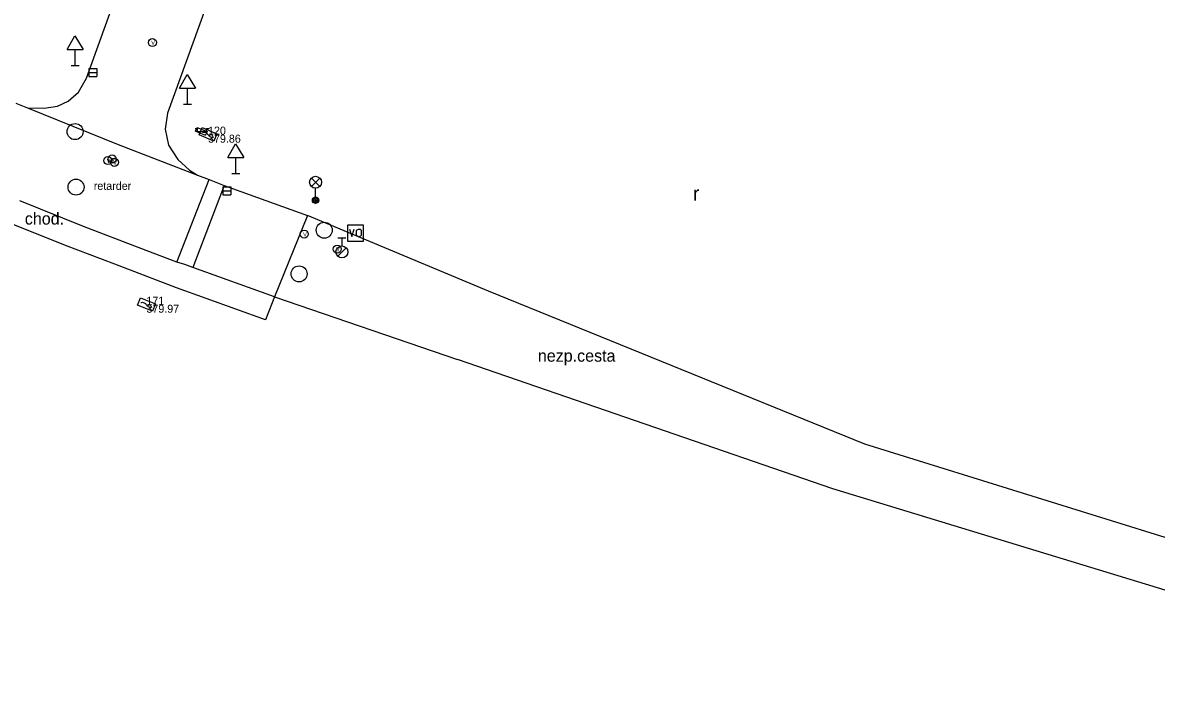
# Model space of a CAD drawing. Extents: x -836568 to -836015, y -1070547 to -1070212.
# Drawn here: x -836298.6 to -836227.7, y -1070464.9 to -1070423.4 of the extents above; entities that cross this region are included whole.
import ezdxf

# ---------------------------------------------------------------- set-up
doc = ezdxf.new("R2010")
doc.units = 0
for name, color, linetype in [('BodPole_mer', 7, 'Continuous'), ('BodPole_popis', 7, 'Continuous'), ('Doprava_body', 7, 'Continuous'), ('Doprava_hranice', 7, 'Continuous'), ('Doprava_kody', 7, 'Continuous'), ('Doprava_popis', 7, 'Continuous'), ('OstPloch_kody', 7, 'Continuous'), ('PovrZnIS_body', 7, 'Continuous'), ('PovrZnIS_hranice', 7, 'Continuous'), ('PovrZnIS_kody', 7, 'Continuous')]:
    doc.layers.add(name, color=color, linetype=linetype)

msp = doc.modelspace()

# ---------------------------------------------------------------- linework, layer by layer
at = {"layer": 'BodPole_mer'}
for p, q in [((-836290.47, -1070424.65), (-836290.47, -1070424.65)), ((-836295.29, -1070426.08), (-836295.29, -1070426.08)), ((-836294.58, -1070426.87), (-836294.58, -1070426.87)), ((-836294.18, -1070426.53), (-836294.18, -1070426.53)), ((-836295.74, -1070428.32), (-836295.74, -1070428.32)), ((-836295.08, -1070427.75), (-836295.08, -1070427.75)), ((-836298.27, -1070428.74), (-836298.27, -1070428.74)), ((-836297.24, -1070428.75), (-836297.24, -1070428.75)), ((-836296.4, -1070428.62), (-836296.4, -1070428.62)), ((-836288.27, -1070428.5), (-836288.27, -1070428.5)), ((-836289.53, -1070429.07), (-836289.53, -1070429.07)), ((-836295.3, -1070430.22), (-836295.3, -1070430.22)), ((-836289.67, -1070430.07), (-836289.67, -1070430.07)), ((-836287.77, -1070430.19), (-836287.77, -1070430.19)), ((-836287.77, -1070430.19), (-836287.77, -1070430.19)), ((-836287.67, -1070429.96), (-836287.67, -1070429.96)), ((-836287.67, -1070429.96), (-836287.67, -1070429.96)), ((-836287.15, -1070430.45), (-836287.15, -1070430.45)), ((-836287.15, -1070430.45), (-836287.15, -1070430.45)), ((-836287.05, -1070430.22), (-836287.05, -1070430.22)), ((-836287.05, -1070430.22), (-836287.05, -1070430.22)), ((-836286.99, -1070430.41), (-836286.99, -1070430.41)), ((-836292.61, -1070431.02), (-836292.61, -1070431.02)), ((-836289.47, -1070431.07), (-836289.47, -1070431.07)), ((-836293.25, -1070432.03), (-836293.25, -1070432.03)), ((-836292.98, -1070431.93), (-836292.98, -1070431.93)), ((-836292.84, -1070432.14), (-836292.84, -1070432.14)), ((-836288.88, -1070431.97), (-836288.88, -1070431.97)), ((-836288.14, -1070432.62), (-836288.14, -1070432.62)), ((-836287.64, -1070432.94), (-836287.64, -1070432.94)), ((-836286.92, -1070433.21), (-836286.92, -1070433.21)), ((-836285.25, -1070432.83), (-836285.25, -1070432.83)), ((-836295.24, -1070433.69), (-836295.24, -1070433.69)), ((-836285.98, -1070433.58), (-836285.98, -1070433.58)), ((-836285.82, -1070433.92), (-836285.82, -1070433.92)), ((-836280.27, -1070434.51), (-836280.27, -1070434.51)), ((-836280.77, -1070435.46), (-836280.77, -1070435.46)), ((-836294.78, -1070436.14), (-836294.78, -1070436.14)), ((-836280.98, -1070436.62), (-836280.98, -1070436.62)), ((-836279.73, -1070436.38), (-836279.73, -1070436.38)), ((-836277.77, -1070436.56), (-836277.77, -1070436.56)), ((-836295.89, -1070437.33), (-836295.89, -1070437.33)), ((-836291.29, -1070437.49), (-836291.29, -1070437.49)), ((-836278.92, -1070437.56), (-836278.92, -1070437.56)), ((-836278.62, -1070437.74), (-836278.62, -1070437.74)), ((-836292.82, -1070438.51), (-836292.82, -1070438.51)), ((-836288.94, -1070438.37), (-836288.94, -1070438.37)), ((-836288.45, -1070438.53), (-836288.45, -1070438.53)), ((-836287.95, -1070438.71), (-836287.95, -1070438.71)), ((-836281.3, -1070439.11), (-836281.3, -1070439.11)), ((-836288.97, -1070439.98), (-836288.97, -1070439.98)), ((-836269.46, -1070440.2), (-836269.46, -1070440.2)), ((-836290.84, -1070441.04), (-836290.84, -1070441.04)), ((-836282.83, -1070440.54), (-836282.83, -1070440.54)), ((-836283.39, -1070441.99), (-836283.39, -1070441.99)), ((-836271.41, -1070444.47), (-836271.41, -1070444.47)), ((-836245.95, -1070449.75), (-836245.95, -1070449.75)), ((-836247.95, -1070452.55), (-836247.95, -1070452.55))]:
    msp.add_line(p, q, dxfattribs=at)
at = {"layer": 'Doprava_body'}
for p, q in [((-836295.79, -1070425.08), (-836295.309, -1070424.226)), ((-836295.309, -1070424.226), (-836294.79, -1070425.08)), ((-836295.79, -1070425.08), (-836294.79, -1070425.08)), ((-836295.29, -1070426.08), (-836295.29, -1070425.08)), ((-836295.54, -1070426.08), (-836295.04, -1070426.08)), ((-836288.77, -1070427.5), (-836288.289, -1070426.646)), ((-836288.289, -1070426.646), (-836287.77, -1070427.5)), ((-836288.77, -1070427.5), (-836287.77, -1070427.5)), ((-836288.27, -1070428.5), (-836288.27, -1070427.5)), ((-836288.52, -1070428.5), (-836288.02, -1070428.5)), ((-836285.75, -1070431.83), (-836285.269, -1070430.976)), ((-836285.269, -1070430.976), (-836284.75, -1070431.83)), ((-836285.75, -1070431.83), (-836284.75, -1070431.83)), ((-836285.25, -1070432.83), (-836285.25, -1070431.83)), ((-836285.5, -1070432.83), (-836285, -1070432.83))]:
    msp.add_line(p, q, dxfattribs=at)
at = {"layer": 'Doprava_hranice'}
for p, q in [((-836288.94, -1070438.37), (-836286.92, -1070433.21)), ((-836285.98, -1070433.58), (-836287.95, -1070438.71)), ((-836269.46, -1070440.2), (-836280.77, -1070435.46)), ((-836282.83, -1070440.54), (-836271.41, -1070444.47))]:
    msp.add_line(p, q, dxfattribs=at)
for points in [[(-836282.83, -1070440.54), (-836283.39, -1070441.99), (-836288.97, -1070439.98), (-836292.82, -1070438.51), (-836295.89, -1070437.33), (-836299.06, -1070436.06), (-836309.56, -1070431.79), (-836314.22, -1070429.91), (-836319.37, -1070427.82), (-836325.29, -1070425.39), (-836329.9, -1070423.52), (-836331.04, -1070426.22), (-836335.67, -1070424.36), (-836334.55, -1070421.64), (-836343.54, -1070417.97), (-836354.29, -1070413.6)], [(-836284.42, -1070414.95), (-836289.53, -1070429.07), (-836289.67, -1070430.07), (-836289.47, -1070431.07), (-836288.88, -1070431.97), (-836288.14, -1070432.62), (-836287.64, -1070432.94)], [(-836298.27, -1070428.74), (-836297.24, -1070428.75), (-836296.4, -1070428.62), (-836295.74, -1070428.32), (-836295.08, -1070427.75), (-836294.58, -1070426.87), (-836292.3, -1070420.51)], [(-836299, -1070428.44), (-836298.27, -1070428.74), (-836292.61, -1070431.02), (-836287.64, -1070432.94), (-836286.92, -1070433.21), (-836285.98, -1070433.58), (-836280.77, -1070435.46), (-836282.83, -1070440.54), (-836287.95, -1070438.71), (-836288.45, -1070438.53), (-836288.94, -1070438.37), (-836291.29, -1070437.49), (-836294.78, -1070436.14), (-836298.75, -1070434.54)], [(-836015.21, -1070459.49), (-836021.84, -1070470.53), (-836029.29, -1070480.55), (-836039.31, -1070497.89), (-836043.1, -1070509.87), (-836044.22, -1070522.08), (-836111.13, -1070487.77), (-836123.74, -1070483.53), (-836128.61, -1070481.99), (-836211.76, -1070460.38), (-836245.95, -1070449.75), (-836269.46, -1070440.2)], [(-836046.6, -1070544.35), (-836045.64, -1070538.23), (-836044.38, -1070528.39), (-836045.14, -1070525.37), (-836047.92, -1070523.71), (-836112.97, -1070490.6), (-836124.66, -1070486.54), (-836132.47, -1070484.33), (-836212.77, -1070463.28), (-836247.95, -1070452.55), (-836271.41, -1070444.47)]]:
    msp.add_lwpolyline(points, dxfattribs=at)
at = {"layer": 'PovrZnIS_body'}
for p, q in [((-836294.43, -1070426.28), (-836293.93, -1070426.28)), ((-836294.43, -1070426.28), (-836294.43, -1070426.78)), ((-836294.43, -1070426.53), (-836293.93, -1070426.53)), ((-836294.43, -1070426.78), (-836293.93, -1070426.78)), ((-836293.93, -1070426.28), (-836293.93, -1070426.78)), ((-836287.548, -1070430.429), (-836287.35, -1070429.97)), ((-836286.629, -1070430.824), (-836287.548, -1070430.429)), ((-836287.35, -1070429.97), (-836286.432, -1070430.365)), ((-836286.432, -1070430.365), (-836286.629, -1070430.824)), ((-836280.535, -1070433.65), (-836280.005, -1070433.12)), ((-836280.535, -1070433.12), (-836280.005, -1070433.65)), ((-836286.07, -1070433.67), (-836285.57, -1070433.67)), ((-836286.07, -1070433.67), (-836286.07, -1070434.17)), ((-836286.07, -1070433.92), (-836285.57, -1070433.92)), ((-836285.57, -1070433.67), (-836285.57, -1070434.17)), ((-836280.27, -1070434.31), (-836280.27, -1070433.76)), ((-836286.07, -1070434.17), (-836285.57, -1070434.17)), ((-836277.27, -1070436.06), (-836278.27, -1070436.06)), ((-836278.27, -1070436.06), (-836278.27, -1070437.06)), ((-836277.27, -1070437.06), (-836277.27, -1070436.06)), ((-836278.355, -1070437.475), (-836278.885, -1070438.005)), ((-836278.87, -1070436.865), (-836278.37, -1070436.865)), ((-836278.62, -1070436.865), (-836278.62, -1070437.365)), ((-836278.27, -1070437.06), (-836277.27, -1070437.06)), ((-836291.397, -1070441.072), (-836291.21, -1070440.608)), ((-836290.47, -1070441.446), (-836291.397, -1070441.072)), ((-836291.21, -1070440.608), (-836290.283, -1070440.983)), ((-836290.283, -1070440.983), (-836290.47, -1070441.446))]:
    msp.add_line(p, q, dxfattribs=at)
for points in [[(-836287.336, -1070430.261), (-836287.288, -1070430.254), (-836287.238, -1070430.253), (-836287.188, -1070430.262), (-836287.138, -1070430.278), (-836287.092, -1070430.303), (-836287.051, -1070430.334), (-836287.017, -1070430.37), (-836286.99, -1070430.41)], [(-836286.99, -1070430.41), (-836286.963, -1070430.45), (-836286.929, -1070430.486), (-836286.888, -1070430.517), (-836286.842, -1070430.541), (-836286.793, -1070430.558), (-836286.743, -1070430.566), (-836286.693, -1070430.566), (-836286.645, -1070430.558)], [(-836278.155, -1070436.317), (-836278.005, -1070436.767)], [(-836278.005, -1070436.767), (-836277.855, -1070436.317)], [(-836277.703, -1070436.401), (-836277.693, -1070436.371), (-836277.67, -1070436.348), (-836277.624, -1070436.327), (-836277.579, -1070436.317), (-836277.519, -1070436.317), (-836277.49, -1070436.325), (-836277.433, -1070436.35), (-836277.413, -1070436.371), (-836277.403, -1070436.401)], [(-836277.703, -1070436.682), (-836277.703, -1070436.401)], [(-836277.703, -1070436.682), (-836277.693, -1070436.713), (-836277.67, -1070436.735), (-836277.624, -1070436.757), (-836277.579, -1070436.767), (-836277.519, -1070436.767), (-836277.49, -1070436.759), (-836277.433, -1070436.733), (-836277.413, -1070436.713), (-836277.403, -1070436.682)], [(-836277.403, -1070436.682), (-836277.403, -1070436.401)], [(-836291.189, -1070440.899), (-836291.142, -1070440.89), (-836291.092, -1070440.889), (-836291.041, -1070440.896), (-836290.991, -1070440.911), (-836290.945, -1070440.935), (-836290.903, -1070440.965), (-836290.868, -1070441.001), (-836290.84, -1070441.04)], [(-836290.84, -1070441.04), (-836290.812, -1070441.079), (-836290.777, -1070441.115), (-836290.736, -1070441.145), (-836290.69, -1070441.168), (-836290.64, -1070441.184), (-836290.589, -1070441.191), (-836290.539, -1070441.189), (-836290.492, -1070441.181)]]:
    msp.add_lwpolyline(points, dxfattribs=at)
for centre, radius in [((-836290.47, -1070424.65), 0.25), ((-836295.3, -1070430.22), 0.5), ((-836293.25, -1070432.03), 0.25), ((-836292.98, -1070431.93), 0.25), ((-836292.84, -1070432.14), 0.25), ((-836295.24, -1070433.69), 0.5), ((-836279.73, -1070436.38), 0.5), ((-836280.98, -1070436.62), 0.25), ((-836278.92, -1070437.56), 0.25), ((-836278.62, -1070437.74), 0.375), ((-836281.3, -1070439.11), 0.5)]:
    msp.add_circle(centre, radius, dxfattribs=at)
for centre, major_axis in [((-836280.27, -1070433.385), (0.375, 0)), ((-836280.27, -1070434.51), (0.2, 0)), ((-836280.266, -1070434.51), (0.125, 0)), ((-836280.266, -1070434.51), (0.05, 0))]:
    msp.add_ellipse(centre, major_axis=major_axis, ratio=0.999998, dxfattribs=at)
at = {"layer": 'PovrZnIS_hranice'}
msp.add_line((-836287.77, -1070430.19), (-836287.15, -1070430.45), dxfattribs=at)
msp.add_line((-836287.77, -1070430.19), (-836287.15, -1070430.45), dxfattribs=at)
msp.add_lwpolyline([(-836287.77, -1070430.19), (-836287.67, -1070429.96), (-836287.05, -1070430.22), (-836287.15, -1070430.45)], dxfattribs=at)
msp.add_lwpolyline([(-836287.77, -1070430.19), (-836287.67, -1070429.96), (-836287.05, -1070430.22), (-836287.15, -1070430.45)], dxfattribs=at)
at = {"layer": 'PovrZnIS_kody'}
for p, q in [((-836287.801, -1070430.02), (-836287.68, -1070430.02)), ((-836287.801, -1070430.02), (-836287.68, -1070430.02)), ((-836287.68, -1070430.02), (-836287.68, -1070430.22)), ((-836287.68, -1070430.02), (-836287.68, -1070430.22)), ((-836287.68, -1070430.22), (-836287.08, -1070430.22)), ((-836287.68, -1070430.22), (-836287.08, -1070430.22)), ((-836287.08, -1070430.22), (-836287.08, -1070430.02)), ((-836287.08, -1070430.02), (-836286.946, -1070430.02)), ((-836287.08, -1070430.22), (-836287.08, -1070430.02)), ((-836287.08, -1070430.02), (-836286.946, -1070430.02))]:
    msp.add_line(p, q, dxfattribs=at)

# ---------------------------------------------------------------- texts
at = {"layer": 'BodPole_popis'}
for s, p in [('379.86', (-836286.99, -1070430.91)), ('120', (-836286.99, -1070430.41)), ('379.97', (-836290.84, -1070441.54)), ('171', (-836290.84, -1070441.04))]:
    msp.add_text(s, height=0.5, dxfattribs=at).set_placement(p)
at = {"layer": 'Doprava_kody'}
for s, p in [('chod.', (-836298.44, -1070436.03)), ('nezp.cesta', (-836266.38, -1070444.6))]:
    msp.add_text(s, height=0.75, dxfattribs=at).set_placement(p)
at = {"layer": 'Doprava_popis'}
msp.add_text('retarder', height=0.5, dxfattribs=at).set_placement((-836294.13, -1070433.86))
at = {"layer": 'OstPloch_kody'}
msp.add_text('r', height=0.9, dxfattribs=at).set_placement((-836256.69, -1070434.53))
at = {"layer": 'PovrZnIS_body'}
for p in [(-836290.541, -1070424.793), (-836293.051, -1070432.073), (-836293.321, -1070432.173), (-836292.911, -1070432.283), (-836281.051, -1070436.763), (-836278.991, -1070437.703)]:
    msp.add_text('V', height=0.25, dxfattribs=at).set_placement(p)

doc.saveas('drawing.dxf')
